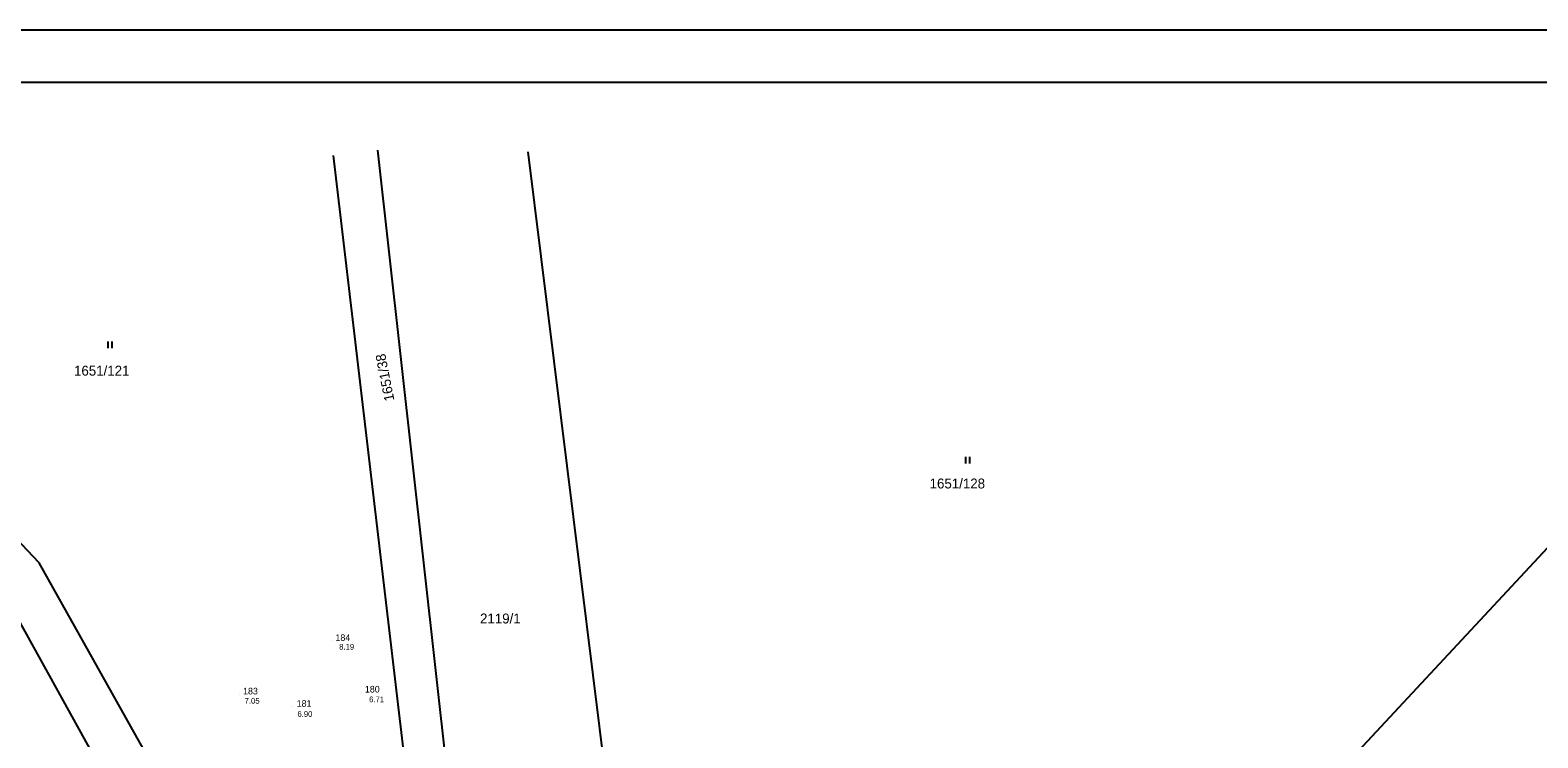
# Model space of a CAD drawing. Extents: x -792549 to -792339, y -1111914 to -1111617.
# Drawn here: x -792498.7 to -792412.2, y -1111657.8 to -1111617.2 of the extents above; entities that cross this region are included whole.
import ezdxf

# ---------------------------------------------------------------- set-up
doc = ezdxf.new("R2010")
doc.units = 0
for name, color, linetype in [('Vrstva 1', 7, 'Continuous'), ('Vrstva 24', 7, 'Continuous'), ('Vrstva 41', 7, 'Continuous'), ('Vrstva 42', 7, 'Continuous'), ('Vrstva 48', 7, 'Continuous'), ('Vrstva 49', 7, 'Continuous'), ('Vrstva 50', 7, 'Continuous'), ('Vrstva 60', 7, 'Continuous')]:
    doc.layers.add(name, color=color, linetype=linetype)

# ---------------------------------------------------------------- blocks, each defined once
blk = doc.blocks.new('3$0600')
at = {"layer": 'Vrstva 1'}
for p, q in [((-5, 15), (-5, 0)), ((5, 0), (5, 15))]:
    blk.add_line(p, q, dxfattribs=at)
blk = doc.blocks.new('SC6231')
at = {"layer": 'Vrstva 1'}
blk.add_line((0, 0), (0, 0), dxfattribs=at)

msp = doc.modelspace()

# ---------------------------------------------------------------- linework, layer by layer
at = {"layer": 'Vrstva 24'}
msp.add_lwpolyline([(-792545.564, -1111620.164), (-792545.564, -1111911.164), (-792341.564, -1111911.164), (-792341.564, -1111620.164)], close=True, dxfattribs=at)
at = {"layer": 'Vrstva 41'}
for p, q in [((-792474.62, -1111681.02), (-792481.274, -1111624.355)), ((-792478.75, -1111624.059), (-792472.48, -1111680.42))]:
    msp.add_line(p, q, dxfattribs=at)
for points in [[(-792462.65, -1111684.23), (-792470.12, -1111624.156)], [(-792523.029, -1111630.747), (-792516.09, -1111635.11), (-792509.06, -1111640.65), (-792500.3, -1111649.32), (-792481.68, -1111682.99), (-792478.83, -1111682.26), (-792498.18, -1111647.73), (-792506.75, -1111638.68), (-792513.86, -1111632.7), (-792526.925, -1111624.621)], [(-792396.21, -1111631.51), (-792404.9, -1111639.66), (-792454.29, -1111692.72), (-792461.78, -1111700.29), (-792461.99, -1111689.5), (-792462.65, -1111684.23), (-792458.31, -1111684.1), (-792457.6, -1111689.12), (-792454.29, -1111692.72)]]:
    msp.add_lwpolyline(points, dxfattribs=at)
at = {"layer": 'Vrstva 60'}
msp.add_lwpolyline([(-792548.564, -1111617.164), (-792548.564, -1111914.164), (-792338.564, -1111914.164), (-792338.564, -1111617.164), (-792548.564, -1111617.164)], dxfattribs=at)

# ---------------------------------------------------------------- block references
at = {"layer": 'Vrstva 42', "xscale": 0.025000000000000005}
for p, yscale, rotation in [((-792494.114, -1111635.41), 0.025000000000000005, 0.17374640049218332), ((-792444.892, -1111642.036), 0.025, 0.09962818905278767)]:
    msp.add_blockref('3$0600', p, dxfattribs=dict(at, yscale=yscale, rotation=rotation))
at = {"layer": 'Vrstva 48', "xscale": 0.1, "yscale": 0.10000000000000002}
for p in [(-792481.35, -1111652.21), (-792486.67, -1111655.28), (-792479.68, -1111655.18), (-792483.7, -1111655.99)]:
    msp.add_blockref('SC6231', p, dxfattribs=at)

# ---------------------------------------------------------------- texts
at = {"layer": 'Vrstva 42'}
for s, p in [('1651/121', (-792496.172, -1111636.994)), ('1651/128', (-792447.073, -1111643.469)), ('2119/1', (-792472.873, -1111651.217))]:
    msp.add_text(s, height=0.57, dxfattribs=at).set_placement(p)
msp.add_text('1651/38', height=0.57, rotation=101.242, dxfattribs=at).set_placement((-792477.786, -1111638.4))
at = {"layer": 'Vrstva 49'}
for s, p in [('184', (-792481.17, -1111652.22)), ('183', (-792486.471, -1111655.29)), ('180', (-792479.481, -1111655.18)), ('181', (-792483.393, -1111656))]:
    msp.add_text(s, height=0.38, dxfattribs=at).set_placement(p)
at = {"layer": 'Vrstva 50'}
for s, p in [('8.19', (-792480.957, -1111652.72)), ('7.05', (-792486.383, -1111655.82)), ('6.71', (-792479.239, -1111655.74)), ('6.90', (-792483.353, -1111656.58))]:
    msp.add_text(s, height=0.33, dxfattribs=at).set_placement(p)

doc.saveas('drawing.dxf')
